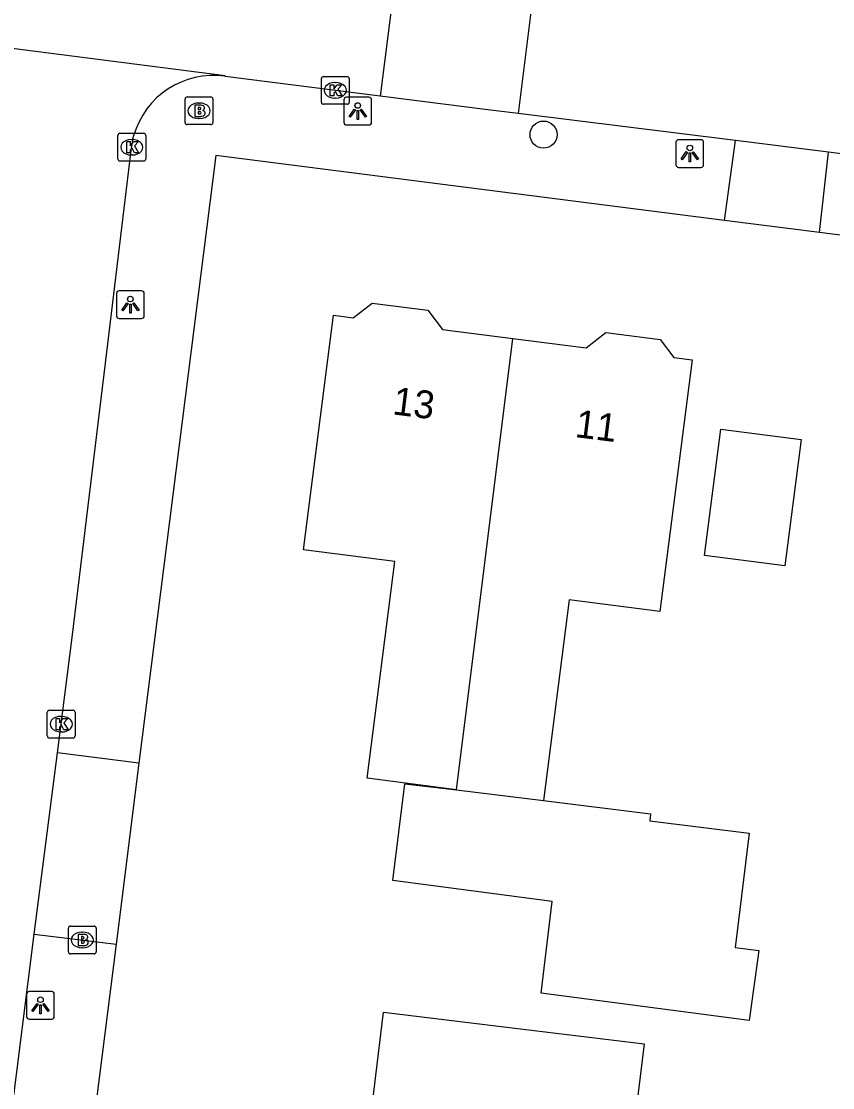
# Model space of a CAD drawing. Extents: x 161258 to 161838, y 380836 to 381727.
# Drawn here: x 161661.92 to 161691.13, y 381300.13 to 381338.52 of the extents above; entities that cross this region are included whole.
import ezdxf

# ---------------------------------------------------------------- set-up
doc = ezdxf.new("R2010")
doc.units = 0
for name, color, linetype in [('IMGEO_Boom', 7, 'Continuous'), ('IMGEO_Brandkraan', 7, 'Continuous'), ('IMGEO_Kolk', 7, 'Continuous'), ('IMGEO_Lichtpunt', 7, 'Continuous'), ('IMGEO_Pand', 7, 'Continuous'), ('IMGEO_Pand_nummerreeks', 7, 'Continuous'), ('IMGEO_Rijbaan_lokaal_open', 7, 'Continuous'), ('IMGEO_Voetpad_open', 7, 'Continuous')]:
    doc.layers.add(name, color=color, linetype=linetype)

msp = doc.modelspace()

# ---------------------------------------------------------------- linework, layer by layer
at = {"layer": 'IMGEO_Boom'}
msp.add_circle((161680.722, 381334.441), 0.489, dxfattribs=at)
at = {"layer": 'IMGEO_Brandkraan'}
for p, q in [((161667.819, 381334.874), (161667.819, 381335.726)), ((161667.894, 381335.8), (161668.746, 381335.8)), ((161668.307, 381335.58), (161668.332, 381335.58)), ((161668.82, 381335.726), (161668.82, 381334.874)), ((161668.33, 381335.02), (161668.305, 381335.02)), ((161668.746, 381334.8), (161667.894, 381334.8)), ((161663.617, 381305.019), (161663.617, 381305.871)), ((161663.692, 381305.945), (161664.544, 381305.945)), ((161664.105, 381305.725), (161664.13, 381305.725)), ((161664.618, 381305.871), (161664.618, 381305.019)), ((161664.544, 381304.945), (161663.692, 381304.945)), ((161664.128, 381305.165), (161664.103, 381305.165))]:
    msp.add_line(p, q, dxfattribs=at)
for points in [[(161667.819, 381334.874), (161667.819, 381335.726)], [(161667.894, 381335.8), (161668.746, 381335.8)], [(161668.82, 381335.726), (161668.82, 381334.874)], [(161668.167, 381335.5), (161668.167, 381335.1), (161668.38, 381335.1)], [(161668.398, 381335.5), (161668.167, 381335.5)], [(161668.346, 381335.419), (161668.292, 381335.419), (161668.292, 381335.343)], [(161668.292, 381335.343), (161668.345, 381335.343)], [(161668.354, 381335.267), (161668.292, 381335.267), (161668.292, 381335.186)], [(161668.292, 381335.186), (161668.354, 381335.186)], [(161668.746, 381334.8), (161667.894, 381334.8)], [(161663.617, 381305.019), (161663.617, 381305.871)], [(161663.692, 381305.945), (161664.544, 381305.945)], [(161663.965, 381305.645), (161663.965, 381305.245), (161664.178, 381305.245)], [(161664.196, 381305.645), (161663.965, 381305.645)], [(161664.618, 381305.871), (161664.618, 381305.019)], [(161664.144, 381305.564), (161664.09, 381305.564), (161664.09, 381305.488)], [(161664.09, 381305.488), (161664.143, 381305.488)], [(161664.152, 381305.412), (161664.09, 381305.412), (161664.09, 381305.331)], [(161664.09, 381305.331), (161664.152, 381305.331)], [(161664.544, 381304.945), (161663.692, 381304.945)]]:
    msp.add_lwpolyline(points, dxfattribs=at)
for centre, radius, start, end in [((161667.896, 381335.724), 0.0765, 91.552, 178.448), ((161667.896, 381335.724), 0.0765, 91.552, 178.448), ((161668.744, 381335.724), 0.0765, 1.552, 88.448), ((161668.744, 381335.724), 0.0765, 1.552, 88.448), ((161668.347, 381335.381), 0.0379, 267.8285, 90.9355), ((161668.355, 381335.226), 0.0404, 269.8759, 90.5077), ((161668.402, 381335.355), 0.145, 59.4692, 91.5367), ((161668.427, 381335.402), 0.0922, 285.5137, 58.1501), ((161668.432, 381335.21), 0.105, 301.3115, 78.989), ((161667.896, 381334.876), 0.0765, 181.552, 268.448), ((161667.896, 381334.876), 0.0765, 181.552, 268.448), ((161668.386, 381335.351), 0.251, 268.6676, 293.5347), ((161668.744, 381334.876), 0.0765, 271.552, 358.448), ((161668.744, 381334.876), 0.0765, 271.552, 358.448), ((161663.694, 381305.869), 0.0765, 91.552, 178.448), ((161663.694, 381305.869), 0.0765, 91.552, 178.448), ((161664.2, 381305.5), 0.145, 59.4692, 91.5367), ((161664.542, 381305.869), 0.0765, 1.552, 88.448), ((161664.542, 381305.869), 0.0765, 1.552, 88.448), ((161664.145, 381305.526), 0.0379, 267.8285, 90.9355), ((161664.153, 381305.371), 0.0404, 269.8759, 90.5077), ((161664.184, 381305.496), 0.251, 268.6676, 293.5347), ((161664.225, 381305.547), 0.0922, 285.5137, 58.1501), ((161664.23, 381305.355), 0.105, 301.3115, 78.989), ((161663.694, 381305.021), 0.0765, 181.552, 268.448), ((161663.694, 381305.021), 0.0765, 181.552, 268.448), ((161664.542, 381305.021), 0.0765, 271.552, 358.448), ((161664.542, 381305.021), 0.0765, 271.552, 358.448)]:
    msp.add_arc(centre, radius, start, end, dxfattribs=at)
for centre, major_axis, ratio, start_param, end_param in [((161668.306, 381335.3), (-0.387, 0.002), 0.722429, 4.712389, 7.853982), ((161668.331, 381335.3), (-0.39, 0.002), 0.717154, 1.570796, 4.712389), ((161664.104, 381305.445), (-0.387, 0.002), 0.722429, 4.712389, 7.853982), ((161664.129, 381305.445), (-0.39, 0.002), 0.717154, 1.570796, 4.712389)]:
    msp.add_ellipse(centre, major_axis=major_axis, ratio=ratio, start_param=start_param, end_param=end_param, dxfattribs=at)
at = {"layer": 'IMGEO_Kolk'}
for p, q in [((161672.724, 381335.608), (161672.724, 381336.46)), ((161672.799, 381336.534), (161673.651, 381336.534)), ((161673.725, 381336.46), (161673.725, 381335.608)), ((161673.212, 381336.314), (161673.237, 381336.314)), ((161673.235, 381335.754), (161673.21, 381335.754)), ((161673.651, 381335.534), (161672.799, 381335.534)), ((161665.475, 381334.488), (161666.327, 381334.488)), ((161665.4, 381333.562), (161665.4, 381334.414)), ((161665.888, 381334.268), (161665.913, 381334.268)), ((161666.401, 381334.414), (161666.401, 381333.562)), ((161665.911, 381333.708), (161665.886, 381333.708)), ((161666.327, 381333.488), (161665.475, 381333.488)), ((161662.935, 381313.715), (161663.787, 381313.715)), ((161662.86, 381312.789), (161662.86, 381313.641)), ((161663.348, 381313.495), (161663.373, 381313.495)), ((161663.861, 381313.641), (161663.861, 381312.789)), ((161663.371, 381312.935), (161663.346, 381312.935)), ((161663.787, 381312.715), (161662.935, 381312.715))]:
    msp.add_line(p, q, dxfattribs=at)
for points in [[(161672.724, 381335.608), (161672.724, 381336.46)], [(161672.799, 381336.534), (161673.651, 381336.534)], [(161673.725, 381336.46), (161673.725, 381335.608)], [(161673.045, 381336.234), (161673.168, 381336.234), (161673.168, 381336.083), (161673.298, 381336.234), (161673.462, 381336.234), (161673.316, 381336.083), (161673.469, 381335.834), (161673.317, 381335.834), (161673.232, 381335.998), (161673.168, 381335.931), (161673.168, 381335.834), (161673.045, 381335.834), (161673.045, 381336.234)], [(161673.651, 381335.534), (161672.799, 381335.534)], [(161665.475, 381334.488), (161666.327, 381334.488)], [(161665.4, 381333.562), (161665.4, 381334.414)], [(161665.721, 381334.188), (161665.844, 381334.188), (161665.844, 381334.037), (161665.974, 381334.188), (161666.138, 381334.188), (161665.992, 381334.037), (161666.145, 381333.788), (161665.993, 381333.788), (161665.908, 381333.952), (161665.844, 381333.885), (161665.844, 381333.788), (161665.721, 381333.788), (161665.721, 381334.188)], [(161666.401, 381334.414), (161666.401, 381333.562)], [(161666.327, 381333.488), (161665.475, 381333.488)], [(161662.935, 381313.715), (161663.787, 381313.715)], [(161662.86, 381312.789), (161662.86, 381313.641)], [(161663.181, 381313.415), (161663.304, 381313.415), (161663.304, 381313.264), (161663.434, 381313.415), (161663.598, 381313.415), (161663.452, 381313.264), (161663.605, 381313.015), (161663.453, 381313.015), (161663.368, 381313.179), (161663.304, 381313.112), (161663.304, 381313.015), (161663.181, 381313.015), (161663.181, 381313.415)], [(161663.861, 381313.641), (161663.861, 381312.789)], [(161663.787, 381312.715), (161662.935, 381312.715)]]:
    msp.add_lwpolyline(points, dxfattribs=at)
for centre, start, end in [((161672.801, 381336.458), 91.552, 178.448), ((161672.801, 381336.458), 91.552, 178.448), ((161673.649, 381336.458), 1.552, 88.448), ((161673.649, 381336.458), 1.552, 88.448), ((161672.801, 381335.61), 181.552, 268.448), ((161672.801, 381335.61), 181.552, 268.448), ((161673.649, 381335.61), 271.552, 358.448), ((161673.649, 381335.61), 271.552, 358.448), ((161665.477, 381334.412), 91.552, 178.448), ((161665.477, 381334.412), 91.552, 178.448), ((161666.325, 381334.412), 1.552, 88.448), ((161666.325, 381334.412), 1.552, 88.448), ((161665.477, 381333.564), 181.552, 268.448), ((161665.477, 381333.564), 181.552, 268.448), ((161666.325, 381333.564), 271.552, 358.448), ((161666.325, 381333.564), 271.552, 358.448), ((161662.937, 381313.639), 91.552, 178.448), ((161662.937, 381313.639), 91.552, 178.448), ((161663.785, 381313.639), 1.552, 88.448), ((161663.785, 381313.639), 1.552, 88.448), ((161662.937, 381312.791), 181.552, 268.448), ((161662.937, 381312.791), 181.552, 268.448), ((161663.785, 381312.791), 271.552, 358.448), ((161663.785, 381312.791), 271.552, 358.448)]:
    msp.add_arc(centre, 0.0765, start, end, dxfattribs=at)
for centre, major_axis, ratio, start_param, end_param in [((161673.211, 381336.034), (-0.387, 0.002), 0.722429, 4.712389, 7.853982), ((161673.236, 381336.034), (-0.39, 0.002), 0.717154, 1.570796, 4.712389), ((161665.887, 381333.988), (-0.387, 0.002), 0.722429, 4.712389, 7.853982), ((161665.912, 381333.988), (-0.39, 0.002), 0.717154, 1.570796, 4.712389), ((161663.347, 381313.215), (-0.387, 0.002), 0.722429, 4.712389, 7.853982), ((161663.372, 381313.215), (-0.39, 0.002), 0.717154, 1.570796, 4.712389)]:
    msp.add_ellipse(centre, major_axis=major_axis, ratio=ratio, start_param=start_param, end_param=end_param, dxfattribs=at)
at = {"layer": 'IMGEO_Lichtpunt'}
for p, q in [((161673.534, 381335.693), (161673.534, 381334.886)), ((161673.534, 381335.693), (161673.534, 381334.886)), ((161674.436, 381335.788), (161673.628, 381335.788)), ((161674.436, 381335.788), (161673.628, 381335.788)), ((161674.53, 381334.886), (161674.53, 381335.693)), ((161674.53, 381334.886), (161674.53, 381335.693)), ((161673.628, 381334.792), (161674.436, 381334.792)), ((161673.628, 381334.792), (161674.436, 381334.792)), ((161685.485, 381334.164), (161685.485, 381333.357)), ((161685.485, 381334.164), (161685.485, 381333.357)), ((161686.387, 381334.259), (161685.579, 381334.259)), ((161686.387, 381334.259), (161685.579, 381334.259)), ((161686.481, 381333.357), (161686.481, 381334.164)), ((161686.481, 381333.357), (161686.481, 381334.164)), ((161685.579, 381333.263), (161686.387, 381333.263)), ((161685.579, 381333.263), (161686.387, 381333.263)), ((161665.351, 381328.722), (161665.351, 381327.915)), ((161665.351, 381328.722), (161665.351, 381327.915)), ((161666.253, 381328.817), (161665.445, 381328.817)), ((161666.253, 381328.817), (161665.445, 381328.817)), ((161666.347, 381327.915), (161666.347, 381328.722)), ((161666.347, 381327.915), (161666.347, 381328.722)), ((161665.445, 381327.821), (161666.253, 381327.821)), ((161665.445, 381327.821), (161666.253, 381327.821)), ((161662.115, 381303.495), (161662.115, 381302.688)), ((161662.115, 381303.495), (161662.115, 381302.688)), ((161663.017, 381303.59), (161662.209, 381303.59)), ((161663.017, 381303.59), (161662.209, 381303.59)), ((161663.111, 381302.688), (161663.111, 381303.495)), ((161663.111, 381302.688), (161663.111, 381303.495)), ((161662.209, 381302.594), (161663.017, 381302.594)), ((161662.209, 381302.594), (161663.017, 381302.594))]:
    msp.add_line(p, q, dxfattribs=at)
for points in [[(161673.908, 381335.357), (161673.947, 381335.329), (161673.759, 381335.067), (161673.721, 381335.094), (161673.908, 381335.357)], [(161674.01, 381335.309), (161674.057, 381335.309), (161674.057, 381334.987), (161674.01, 381334.987), (161674.01, 381335.309)], [(161674.12, 381335.329), (161674.158, 381335.356), (161674.345, 381335.094), (161674.306, 381335.066), (161674.12, 381335.329)], [(161685.859, 381333.828), (161685.898, 381333.8), (161685.71, 381333.538), (161685.672, 381333.565), (161685.859, 381333.828)], [(161685.961, 381333.78), (161686.008, 381333.78), (161686.008, 381333.458), (161685.961, 381333.458), (161685.961, 381333.78)], [(161686.071, 381333.8), (161686.109, 381333.827), (161686.296, 381333.565), (161686.257, 381333.537), (161686.071, 381333.8)], [(161665.725, 381328.386), (161665.764, 381328.358), (161665.576, 381328.096), (161665.538, 381328.123), (161665.725, 381328.386)], [(161665.827, 381328.338), (161665.874, 381328.338), (161665.874, 381328.016), (161665.827, 381328.016), (161665.827, 381328.338)], [(161665.937, 381328.358), (161665.975, 381328.385), (161666.162, 381328.123), (161666.123, 381328.095), (161665.937, 381328.358)], [(161662.489, 381303.159), (161662.528, 381303.131), (161662.34, 381302.869), (161662.302, 381302.896), (161662.489, 381303.159)], [(161662.591, 381303.111), (161662.638, 381303.111), (161662.638, 381302.789), (161662.591, 381302.789), (161662.591, 381303.111)], [(161662.701, 381303.131), (161662.739, 381303.158), (161662.926, 381302.896), (161662.887, 381302.868), (161662.701, 381303.131)]]:
    msp.add_lwpolyline(points, dxfattribs=at)
for centre in [(161674.033, 381335.491), (161685.984, 381333.962), (161665.85, 381328.52), (161662.614, 381303.293)]:
    msp.add_circle(centre, 0.0994, dxfattribs=at)
for centre, start, end in [((161673.628, 381335.693), 90, 180), ((161673.628, 381335.693), 90, 180), ((161674.436, 381335.693), 0, 90), ((161674.436, 381335.693), 0, 90), ((161673.628, 381334.886), 180, 270), ((161673.628, 381334.886), 180, 270), ((161674.436, 381334.886), 270, 0), ((161674.436, 381334.886), 270, 360), ((161685.579, 381334.164), 90, 180), ((161685.579, 381334.164), 90, 180), ((161686.387, 381334.164), 0, 90), ((161686.387, 381334.164), 0, 90), ((161685.579, 381333.357), 180, 270), ((161685.579, 381333.357), 180, 270), ((161686.387, 381333.357), 270, 0), ((161686.387, 381333.357), 270, 360), ((161665.445, 381328.722), 90, 180), ((161665.445, 381328.722), 90, 180), ((161666.253, 381328.722), 0, 90), ((161666.253, 381328.722), 0, 90), ((161665.445, 381327.915), 180, 270), ((161665.445, 381327.915), 180, 270), ((161666.253, 381327.915), 270, 0), ((161666.253, 381327.915), 270, 360), ((161662.209, 381303.495), 90, 180), ((161662.209, 381303.495), 90, 180), ((161663.017, 381303.495), 0, 90), ((161663.017, 381303.495), 0, 90), ((161662.209, 381302.688), 180, 270), ((161662.209, 381302.688), 180, 270), ((161663.017, 381302.688), 270, 0), ((161663.017, 381302.688), 270, 360)]:
    msp.add_arc(centre, 0.0946, start, end, dxfattribs=at)
at = {"layer": 'IMGEO_Pand'}
for points in [[(161677.592, 381310.853), (161674.367, 381311.267), (161675.369, 381319.074), (161672.081, 381319.497), (161673.165, 381327.939), (161673.871, 381327.848), (161674.555, 381328.376), (161676.553, 381328.12), (161677.088, 381327.426), (161679.613, 381327.102)], [(161679.613, 381327.102), (161682.251, 381326.763), (161682.96, 381327.311), (161684.912, 381327.061), (161685.41, 381326.416), (161686.071, 381326.331), (161685.434, 381321.372), (161684.908, 381317.277), (161681.648, 381317.696), (161680.721, 381310.465)], [(161677.592, 381310.853), (161679.613, 381327.102)], [(161686.511, 381319.288), (161687.096, 381323.842), (161689.99, 381323.47), (161689.405, 381318.916), (161686.511, 381319.288)], [(161680.721, 381310.465), (161684.573, 381309.988), (161684.542, 381309.73), (161688.116, 381309.294), (161687.709, 381305.958), (161687.614, 381305.174), (161688.468, 381305.07), (161688.127, 381302.546), (161680.632, 381303.526), (161681.035, 381306.831), (161675.298, 381307.582), (161675.723, 381311.067), (161677.592, 381310.853)], [(161677.592, 381310.853), (161680.721, 381310.465)], [(161674.024, 381295.74), (161673.11, 381295.857), (161673.203, 381296.622), (161674.187, 381296.502), (161674.963, 381302.849), (161679.982, 381302.235), (161684.343, 381301.701), (161683.468, 381294.548)]]:
    msp.add_lwpolyline(points, dxfattribs=at)
at = {"layer": 'IMGEO_Rijbaan_lokaal_open'}
for points in [[(161675.625, 381341.974), (161674.844, 381335.829)], [(161680.569, 381341.362), (161679.804, 381335.202)], [(161669.258, 381336.54), (161669.261, 381336.557), (161657.935, 381338.014)], [(161674.844, 381335.829), (161669.258, 381336.54)], [(161679.804, 381335.202), (161678.715, 381335.337), (161674.844, 381335.829)], [(161687.626, 381334.23), (161679.804, 381335.202)], [(161663.227, 381312.185), (161663.76, 381316.338), (161664.948, 381326.215), (161665.881, 381333.874), (161665.965, 381334.393)], [(161690.979, 381333.814), (161687.626, 381334.23)], [(161700.036, 381332.619), (161690.979, 381333.814)], [(161662.388, 381305.648), (161663.227, 381312.185)], [(161659.96, 381287.198), (161661.538, 381298.881), (161662.388, 381305.648)]]:
    msp.add_lwpolyline(points, dxfattribs=at)
msp.add_arc((161668.838, 381333.585), 2.985, 81.9202, 164.2876, dxfattribs=at)
at = {"layer": 'IMGEO_Voetpad_open'}
for points in [[(161687.235, 381331.354), (161687.626, 381334.23)], [(161687.235, 381331.354), (161668.929, 381333.694), (161666.159, 381311.809)], [(161690.653, 381330.917), (161690.979, 381333.814)], [(161690.653, 381330.917), (161687.235, 381331.354)], [(161703.558, 381329.267), (161690.653, 381330.917)], [(161666.159, 381311.809), (161663.227, 381312.185)], [(161666.159, 381311.809), (161665.334, 381305.29)], [(161662.388, 381305.648), (161665.334, 381305.29)], [(161665.334, 381305.29), (161663, 381286.849)]]:
    msp.add_lwpolyline(points, dxfattribs=at)

# ---------------------------------------------------------------- texts
at = {"layer": 'IMGEO_Pand_nummerreeks'}
for s, p in [('13', (161675.257, 381324.373)), ('11', (161681.823, 381323.555))]:
    msp.add_text(s, height=1, rotation=352.8979, dxfattribs=at).set_placement(p)

doc.saveas('drawing.dxf')
